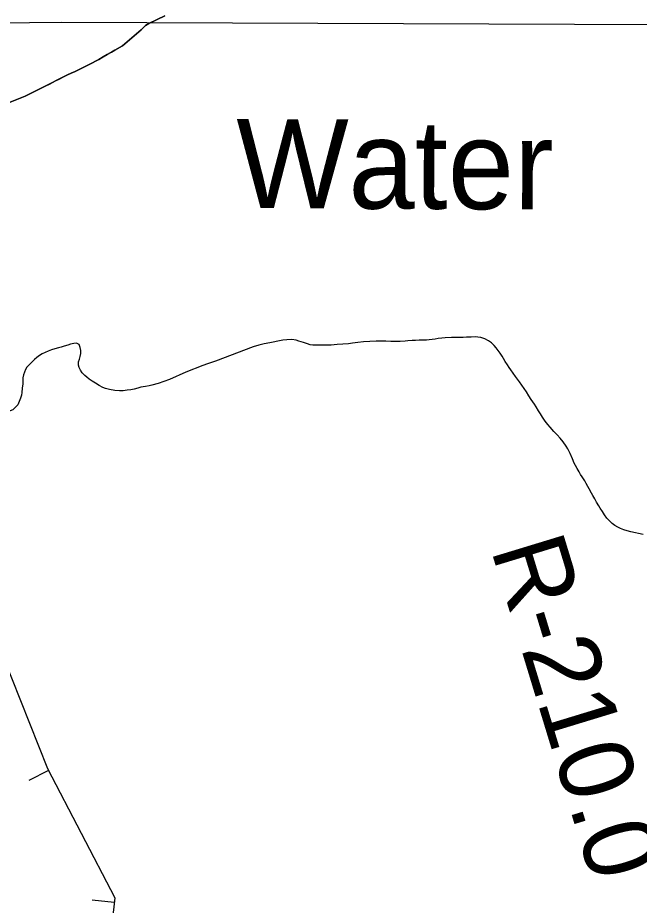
# Model space of a CAD drawing. Extents: x 3297753 to 3335611, y 652252 to 677623.
# Drawn here: x 3316892 to 3317590, y 662100 to 663097 of the extents above; entities that cross this region are included whole.
import ezdxf

# ---------------------------------------------------------------- set-up
doc = ezdxf.new("R2010")
doc.units = 0
for name, color, linetype in [('V-BORW-LINE', 7, 'Continuous'), ('V-RIVR-IDEN', 7, 'Continuous'), ('V-RIVR-RANG-IDEN', 7, 'Continuous'), ('V-RRAP-FSHR', 7, 'Continuous'), ('V-SITE-VEGE', 7, 'Continuous'), ('V-TOPO-BNDY', 7, 'Continuous'), ('V-TOPO-SHOR', 7, 'Continuous'), ('V-WETL-SWMP', 7, 'Continuous')]:
    doc.layers.add(name, color=color, linetype=linetype)

msp = doc.modelspace()

# ---------------------------------------------------------------- linework, layer by layer
at = {"layer": 'V-BORW-LINE'}
for p, q in [((3316926.47, 662251.33), (3316904.28, 662239.81)), ((3317000.2, 662102.89), (3316975.36, 662105.71))]:
    msp.add_line(p, q, dxfattribs=at)
msp.add_lwpolyline([(3315093.24, 666333.57), (3315370.65, 665800.89), (3315694.88, 665090.77), (3316008.53, 664407.77), (3316316.24, 663756.03), (3316554.81, 663176.74), (3316744.77, 662671.92), (3316833.93, 662482.66), (3316925.39, 662253.41), (3317000.79, 662108.07), (3316991.78, 662028.57), (3316842.01, 661998.3), (3316747.67, 662044.12), (3316706.74, 662117.51)], dxfattribs=at)
at = {"layer": 'V-RRAP-FSHR'}
msp.add_spline([(3320150.09, 662315.57), (3320047.66, 662286.07), (3319931.17, 662251.44), (3319796.75, 662213.62), (3319527.39, 662140.55), (3319274.19, 662042.74), (3319037.81, 661963.73), (3318810.27, 661886.82), (3318640.56, 661831.26), (3318442.36, 661771.51), (3318223.46, 661674.42), (3318125.37, 661625.89), (3317894.87, 661465.55), (3317737.05, 661336.67), (3317612.9, 661222.68), (3317433.81, 661109.89), (3317347.16, 661063.4), (3317219.78, 661006.27), (3317048.57, 660941.68), (3316920.5, 660895.56), (3316802.75, 660835.25), (3316727.52, 660743.33), (3316559.69, 660646.41), (3316447.95, 660562.27), (3316323.7, 660479.21), (3316253.56, 660449.94), (3316120.17, 660384.24), (3315999.77, 660284.17), (3315912.51, 660202.12), (3315858.05, 660160.36)], degree=3, dxfattribs=at)
at = {"layer": 'V-SITE-VEGE'}
for p, q in [((3317057.15, 663098.78), (3317039.11, 663090.34)), ((3317032.9, 663085.91), (3317030.42, 663083.33)), ((3317035.18, 663087.86), (3317032.9, 663085.91)), ((3317039.11, 663090.34), (3317035.18, 663087.86)), ((3317030.42, 663083.33), (3317009.52, 663065.27)), ((3316992.24, 663055.38), (3316987.9, 663052.7)), ((3317009.52, 663065.27), (3316992.24, 663055.38)), ((3316982.83, 663049.92), (3316971.97, 663044.25)), ((3316987.9, 663052.7), (3316982.83, 663049.92)), ((3316956.15, 663036.53), (3316951.9, 663034.67)), ((3316971.97, 663044.25), (3316956.15, 663036.53)), ((3316943.22, 663030.45), (3316923.25, 663020.15)), ((3316951.9, 663034.67), (3316943.22, 663030.45)), ((3316923.25, 663020.15), (3316900.19, 663008.71)), ((3316900.19, 663008.71), (3316881.57, 663000.99))]:
    msp.add_line(p, q, dxfattribs=at)
at = {"layer": 'V-TOPO-BNDY'}
for p, q in [((3316371.29, 663084.98), (3316940.98, 663091.7)), ((3316940.98, 663091.7), (3324715.94, 663061.38))]:
    msp.add_line(p, q, dxfattribs=at)
at = {"layer": 'V-TOPO-SHOR'}
for points in [[(3316947.77, 663032.72), (3316951.9, 663034.67), (3316956.15, 663036.53), (3316971.97, 663044.25), (3316982.83, 663049.92), (3316987.9, 663052.7), (3316992.24, 663055.38), (3316997.1, 663058.16), (3317000.93, 663060.33), (3317009.52, 663065.27), (3317030.42, 663083.33), (3317032.9, 663085.91), (3317035.18, 663087.86), (3317039.11, 663090.34), (3317057.15, 663098.78)], [(3316881.58, 663000.99), (3316900.19, 663008.71), (3316923.25, 663020.15), (3316927.5, 663022.31), (3316931.53, 663024.47), (3316934.22, 663025.82), (3316938.25, 663027.88), (3316943.22, 663030.45), (3316947.77, 663032.72)], [(3317388.2, 662737.68), (3317384.38, 662737.58), (3317378.9, 662737.59), (3317371.98, 662737.29), (3317367.95, 662736.89), (3317364.02, 662736.38), (3317360.61, 662735.86), (3317357.19, 662735.35), (3317353.78, 662734.94), (3317350.79, 662734.74), (3317347.48, 662734.64), (3317342.52, 662734.45), (3317338.39, 662734.14), (3317334.77, 662734.15), (3317329.81, 662733.95), (3317326.81, 662733.54), (3317321.43, 662733.24), (3317316.68, 662733.14), (3317310.89, 662733.26), (3317305.21, 662733.37), (3317298.8, 662733.38), (3317294.46, 662733.28), (3317287.12, 662733.09), (3317280.3, 662732.58), (3317273.58, 662731.87), (3317267.8, 662731.16), (3317263.35, 662730.54), (3317256.84, 662729.93), (3317250.43, 662729.53), (3317243.92, 662729.13), (3317238.44, 662728.93), (3317235.24, 662728.93), (3317231.1, 662728.94), (3317226.15, 662728.84), (3317223.15, 662729.06), (3317220.15, 662729.37), (3317217.26, 662730.31), (3317212.72, 662731.86), (3317207.45, 662733.63), (3317204.45, 662734.56), (3317199.49, 662735.4), (3317194.02, 662735.1), (3317189.37, 662734.59), (3317183.78, 662733.46), (3317178.61, 662732.33), (3317174.99, 662731.72), (3317168.48, 662730.49), (3317162.49, 662729.05), (3317156.28, 662727.2), (3317113.78, 662711.15), (3317108.41, 662709.29), (3317104.99, 662707.96), (3317099.62, 662706), (3317080.69, 662698.8), (3317062.28, 662690.35), (3317055.98, 662688.09), (3317049.36, 662685.83), (3317042.43, 662684.08), (3317039.44, 662683.36), (3317035.2, 662682.54), (3317030.03, 662681.62), (3317026.51, 662680.7), (3317022.38, 662679.57), (3317018.76, 662678.85), (3317014.62, 662678.23), (3317010.39, 662677.83), (3317006.25, 662677.63), (3317000.98, 662678.05), (3316994.89, 662678.99), (3316990.55, 662680.34), (3316987.45, 662681.48), (3316983.32, 662683.76), (3316979.19, 662686.35), (3316975.47, 662688.53), (3316972.17, 662690.81), (3316969.48, 662692.88), (3316967.01, 662694.95), (3316964.22, 662697.74), (3316962.37, 662700.85), (3316960.93, 662703.74), (3316960, 662706.64), (3316960.21, 662710.36), (3316961.04, 662713.35), (3316962.08, 662716.35), (3316962.5, 662719.76), (3316962.51, 662722.86), (3316962, 662726.27), (3316960.66, 662729.79), (3316957.87, 662731.13), (3316954.66, 662730.83), (3316951.05, 662729.91), (3316948.05, 662728.88), (3316944.12, 662727.75), (3316940.6, 662726.72), (3316937.4, 662725.9), (3316933.57, 662724.66), (3316929.85, 662723.63), (3316926.13, 662722.3), (3316922.61, 662720.85), (3316919.3, 662719.21), (3316916.41, 662717.45)], [(3317594.33, 662516.19), (3317580.38, 662519.21), (3317576.15, 662520.36), (3317572.43, 662521.5), (3317568.71, 662522.95), (3317565.82, 662524.51), (3317562.52, 662526.47), (3317559.52, 662528.76), (3317556.32, 662531.55), (3317553.54, 662534.76), (3317550.85, 662538.38), (3317548.49, 662542), (3317546.01, 662545.72), (3317544.46, 662548.31), (3317541.79, 662552.66), (3317539.83, 662556.17), (3317537.56, 662560.21), (3317536.01, 662562.9), (3317533.64, 662567.45), (3317532.1, 662570.03), (3317530.14, 662573.76), (3317528.6, 662576.55), (3317525.6, 662581.2), (3317523.96, 662583.79), (3317522.2, 662586.79), (3317520.14, 662590.41), (3317518.19, 662593.72), (3317516.64, 662596.51), (3317514.89, 662601.37), (3317512.21, 662607.37), (3317509.43, 662612.34), (3317507.78, 662615.54), (3317504.38, 662620.41), (3317500.97, 662624.34), (3317497.78, 662628.06), (3317493.96, 662632.1), (3317489.73, 662636.96), (3317487.25, 662639.76), (3317484.27, 662643.59), (3317481.17, 662648.03), (3317478.8, 662651.76), (3317476.53, 662655.38), (3317473.96, 662659.52), (3317472, 662662.52), (3317468.49, 662667.9), (3317465.91, 662672.14), (3317463.03, 662676.59), (3317460.56, 662680.41), (3317457.87, 662684.14), (3317455.19, 662687.76), (3317453.13, 662690.66), (3317450.96, 662693.66), (3317448.28, 662697.59), (3317445.71, 662701.11), (3317443.64, 662704), (3317441.69, 662707.01), (3317439.31, 662710.62), (3317437.46, 662713.83), (3317435.91, 662716.42), (3317433.44, 662720.04), (3317431.38, 662723.04), (3317429.11, 662726.04), (3317426.73, 662728.73), (3317423.85, 662731.42), (3317420.34, 662733.91), (3317416.31, 662736.08), (3317411.97, 662737.54), (3317408.67, 662738.06), (3317405.36, 662738.27), (3317401.12, 662738.07), (3317395.95, 662737.87), (3317392.23, 662737.67), (3317388.2, 662737.68)], [(3316916.41, 662717.45), (3316913.2, 662715.29), (3316910.72, 662713.02), (3316907.82, 662710.13), (3316904.4, 662706.62), (3316902.12, 662704.15), (3316900.47, 662701.46), (3316899.33, 662698.57), (3316898.39, 662695.58), (3316897.66, 662692.37), (3316897.55, 662689.17), (3316897.34, 662685.35), (3316896.92, 662680.8), (3316896.29, 662675.84), (3316895.87, 662672.74), (3316894.83, 662669.54), (3316893.59, 662665.61), (3316892.03, 662662.1), (3316886.12, 662656.39), (3316879.17, 662653.81)]]:
    msp.add_lwpolyline(points, dxfattribs=at)
at = {"layer": 'V-WETL-SWMP'}
for p, q in [((3317057.15, 663098.77), (3317039.11, 663090.34)), ((3317032.9, 663085.9), (3317030.42, 663083.32)), ((3317035.18, 663087.86), (3317032.9, 663085.9)), ((3317039.11, 663090.34), (3317035.18, 663087.86)), ((3317030.42, 663083.32), (3317009.51, 663065.27)), ((3316992.24, 663055.38), (3316987.9, 663052.7)), ((3316997.1, 663058.16), (3316992.24, 663055.38)), ((3317000.93, 663060.33), (3316997.1, 663058.16)), ((3317009.51, 663065.27), (3317000.93, 663060.33)), ((3316982.83, 663049.92), (3316971.97, 663044.25)), ((3316987.9, 663052.7), (3316982.83, 663049.92)), ((3316956.14, 663036.53), (3316951.9, 663034.67)), ((3316971.97, 663044.25), (3316956.14, 663036.53)), ((3316934.22, 663025.81), (3316931.53, 663024.47)), ((3316938.25, 663027.87), (3316934.22, 663025.81)), ((3316943.22, 663030.45), (3316938.25, 663027.87)), ((3316947.77, 663032.71), (3316943.22, 663030.45)), ((3316951.9, 663034.67), (3316947.77, 663032.71)), ((3316923.25, 663020.15), (3316900.19, 663008.71)), ((3316927.49, 663022.31), (3316923.25, 663020.15)), ((3316931.53, 663024.47), (3316927.49, 663022.31)), ((3316900.19, 663008.71), (3316881.58, 663000.99))]:
    msp.add_line(p, q, dxfattribs=at)

# ---------------------------------------------------------------- texts
at = {"layer": 'V-RIVR-IDEN'}
msp.add_text('Water', height=100, rotation=359.72437, dxfattribs=at).set_placement((3317136.84, 662883.07))
at = {"layer": 'V-RIVR-RANG-IDEN'}
msp.add_text('R-210.0', height=83, rotation=286.95664, dxfattribs=at).set_placement((3317422.85, 662499.99))

doc.saveas('drawing.dxf')
